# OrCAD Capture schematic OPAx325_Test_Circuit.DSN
size A; title: OPAx325 Precision, 10-MHz, Low-Noise, Low-Power, RRIO,; rev: 1.3; note: Datasheet: SBOS637D  EVM: N/A
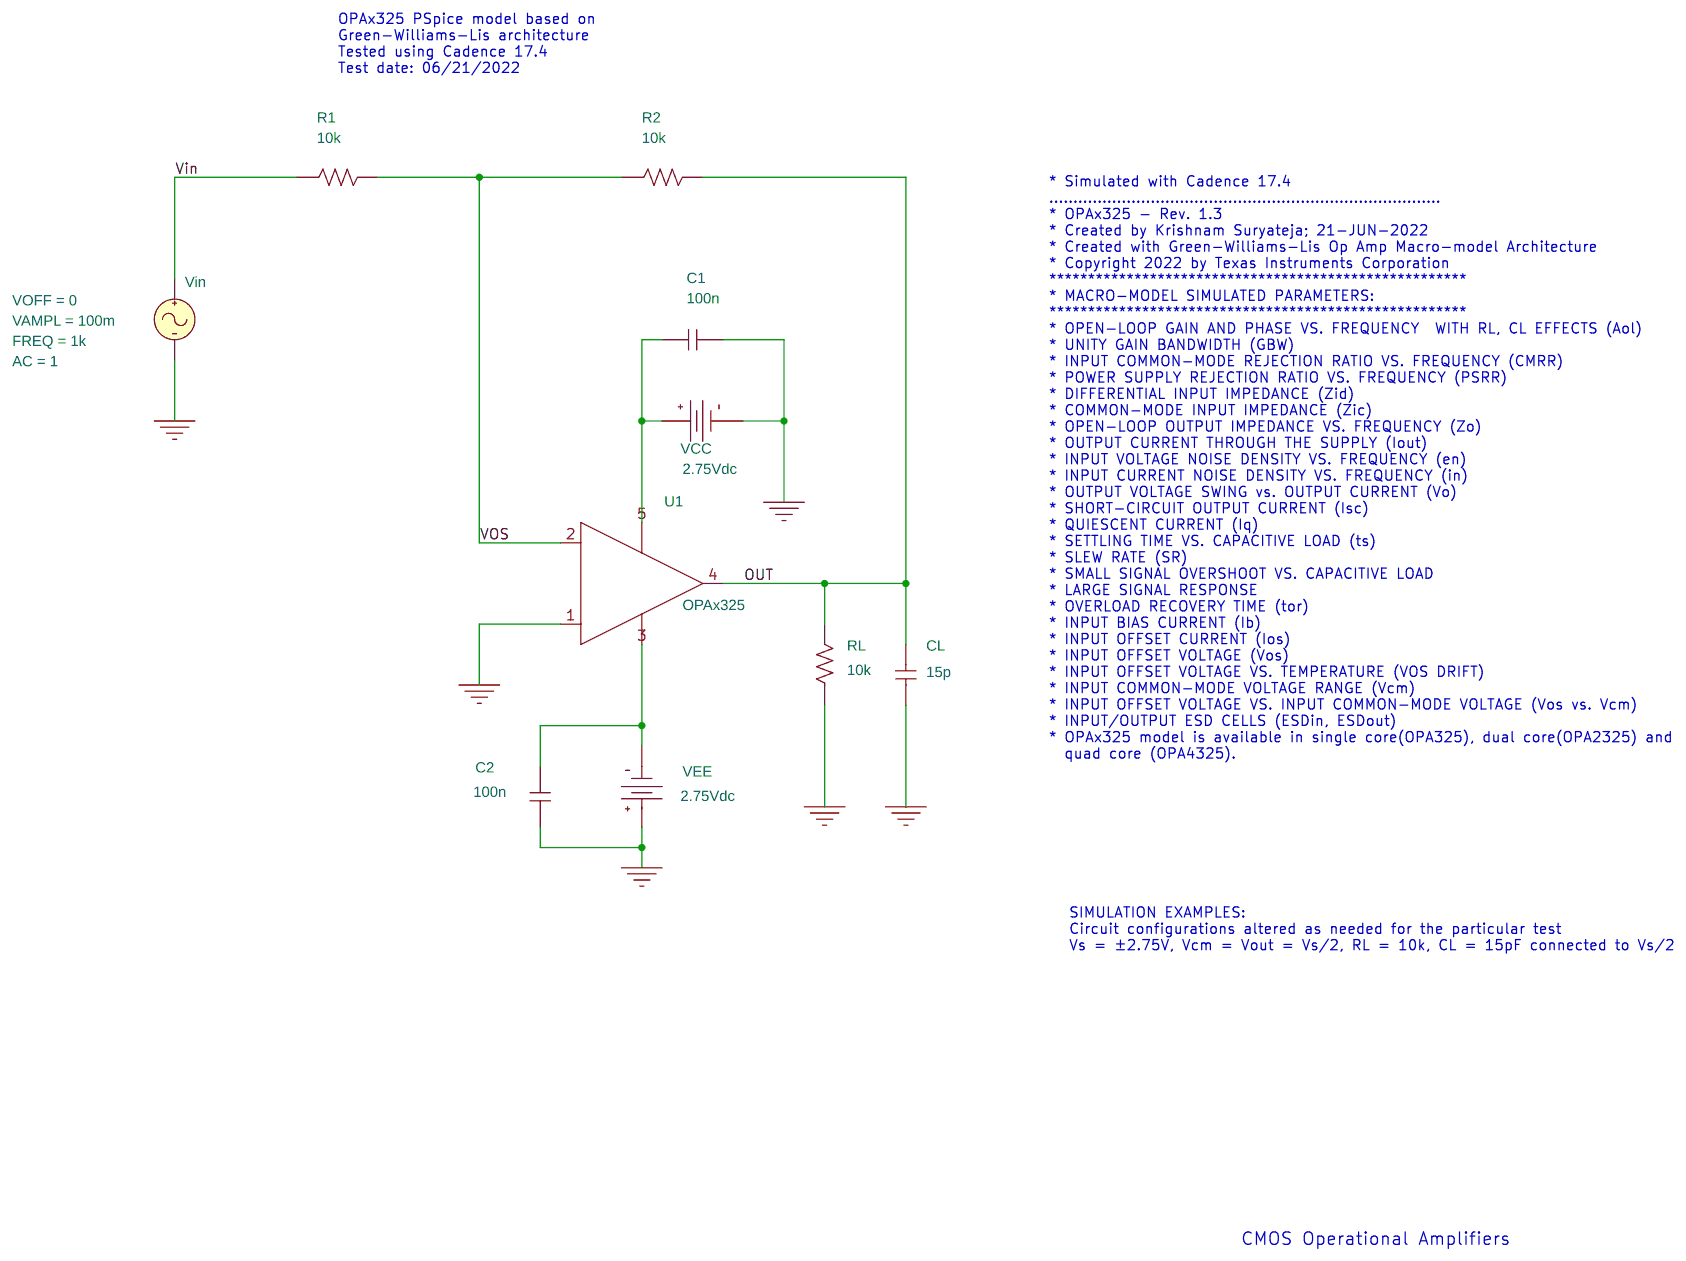
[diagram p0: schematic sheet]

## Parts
C1  100n  [cap196]
C2  100n  [cap196]
CL  15p  [cap196]
R1  10k  [AXRC05]
R2  10k  [AXRC05]
RL  10k  [AXRC05]
U1  OPAx325
VCC  VDC
VEE  VDC
Vin  VSIN

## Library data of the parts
C1 C2 CL = C
R1 R2 RL = R
U1 = OPAx325
VCC VEE = VDC: DC: 2.75Vdc
Vin = VSIN: AC: 1; FREQ: 1k; VAMPL: 100m; VOFF: 0

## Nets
Vin: R1.1 Vin.1(+)
0: C1.2 C2.1 CL.2 RL.1 U1.1(+) VCC.1(-) VEE.0(+) Vin.2(-)
OUT: CL.1 R2.2 RL.2 U1.4(OUT)
VOS: R1.2 R2.1 U1.2(-)
N27303: C1.1 U1.5(V+) VCC.0(+)
N27354: C2.2 U1.3(V-) VEE.1(-)

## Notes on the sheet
- OPAx325 PSpice model based on
  Green-Williams-Lis architecture
  Tested using Cadence 17.4
  Test date: 06/21/2022
- * Simulated with Cadence 17.4
  .................................................................................
  * OPAx325 - Rev. 1.3
  * Created by Krishnam Suryateja; 21-JUN-2022
  * Created with Green-Williams-Lis Op Amp Macro-model Architecture
  * Copyright 2022 by Texas Instruments Corporation
  ******************************************************
  * MACRO-MODEL SIMULATED PARAMETERS:
  ******************************************************
  * OPEN-LOOP GAIN AND PHASE VS. FREQUENCY  WITH RL, CL EFFECTS (Aol)
  * UNITY GAIN BANDWIDTH (GBW)
  * INPUT COMMON-MODE REJECTION RATIO VS. FREQUENCY (CMRR)
  * POWER SUPPLY REJECTION RATIO VS. FREQUENCY (PSRR)
  * DIFFERENTIAL INPUT IMPEDANCE (Zid)
  * COMMON-MODE INPUT IMPEDANCE (Zic)
  * OPEN-LOOP OUTPUT IMPEDANCE VS. FREQUENCY (Zo)
  * OUTPUT CURRENT THROUGH THE SUPPLY (Iout)
  * INPUT VOLTAGE NOISE DENSITY VS. FREQUENCY (en)
  * INPUT CURRENT NOISE DENSITY VS. FREQUENCY (in)
  * OUTPUT VOLTAGE SWING vs. OUTPUT CURRENT (Vo)
  * SHORT-CIRCUIT OUTPUT CURRENT (Isc)
  * QUIESCENT CURRENT (Iq)
  * SETTLING TIME VS. CAPACITIVE LOAD (ts)
  * SLEW RATE (SR)
  * SMALL SIGNAL OVERSHOOT VS. CAPACITIVE LOAD
  * LARGE SIGNAL RESPONSE
  * OVERLOAD RECOVERY TIME (tor)
  * INPUT BIAS CURRENT (Ib)
  * INPUT OFFSET CURRENT (Ios)
  * INPUT OFFSET VOLTAGE (Vos)
  * INPUT OFFSET VOLTAGE VS. TEMPERATURE (VOS DRIFT)
  * INPUT COMMON-MODE VOLTAGE RANGE (Vcm)
  * INPUT OFFSET VOLTAGE VS. INPUT COMMON-MODE VOLTAGE (Vos vs. Vcm)
  * INPUT/OUTPUT ESD CELLS (ESDin, ESDout)
  * OPAx325 model is available in single core(OPA325), dual core(OPA2325) and
    quad core (OPA4325).
- SIMULATION EXAMPLES:
  Circuit configurations altered as needed for the particular test
  Vs = ±2.75V, Vcm = Vout = Vs/2, RL = 10k, CL = 15pF connected to Vs/2
- CMOS Operational Amplifiers
